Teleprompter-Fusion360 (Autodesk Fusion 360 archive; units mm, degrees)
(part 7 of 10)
sketch "Skizze89" plane through (0, 0, 0) normal (0, 0, -1) x axis (1, 0, 0)
  line L1 (137.0031, -323.7) -> (137.0031, -279.3404)
  line L2 (154.0031, -323.7) -> (137.0031, -323.7)
  line L3 (154.0031, -311.7) -> (154.0031, -323.7)
  line L4 (171.0031, -311.7) -> (154.0031, -311.7)
  line L5 (171.0031, -323.7) -> (171.0031, -311.7)
  line L6 (188.0031, -323.7) -> (171.0031, -323.7)
  line L7 (188.0031, -311.7) -> (188.0031, -323.7)
  line L8 (205.0031, -311.7) -> (188.0031, -311.7)
  line L9 (205.0031, -323.7) -> (205.0031, -311.7)
  line L10 (222.0031, -323.7) -> (205.0031, -323.7)
  line L11 (222.0031, -279.3404) -> (222.0031, -323.7)
  line L12 (374.0031, -255.3404) -> (246.0031, -255.3404)
  line L13 (374.0031, -240.1877) -> (374.0031, -255.3404)
  line L14 (366.2457, -240.1877) -> (374.0031, -240.1877)
  line L15 (362.0031, -220.3404) -> (362.0031, -235.9451)
  line L16 (361.0031, -220.3404) -> (362.0031, -220.3404)
  line L17 (358.0031, -167.3404) -> (358.0031, -217.3404)
  line L18
  line L19 (362.0031, -134.383) -> (362.0031, -164.3404)
  line L20 (374.0031, -130.1404) -> (366.2457, -130.1404)
  line L21 (374.0031, -95.9404) -> (374.0031, -130.1404)
  line L22 (366.2457, -95.9404) -> (374.0031, -95.9404)
  line L23 (362.0031, -65.983) -> (362.0031, -91.6977)
  line L24 (374.0031, -61.7404) -> (366.2457, -61.7404)
  line L25 (374.0031, -27.5404) -> (374.0031, -61.7404)
  line L26 (366.2457, -27.5404) -> (374.0031, -27.5404)
  line L27 (362.0031, 2.417) -> (362.0031, -23.2977)
  line L28 (374.0031, 6.6596) -> (366.2457, 6.6596)
  line L29 (-2.9969, 18.6596) -> (362.0031, 18.6596)
  line L30 (-7.2396, 6.6596) -> (-14.9969, 6.6596)
  line L31 (-2.9969, -23.2977) -> (-2.9969, 2.417)
  line L32 (-14.9969, -27.5404) -> (-7.2396, -27.5404)
  line L33 (-14.9969, -61.7404) -> (-14.9969, -27.5404)
  line L34 (-7.2396, -61.7404) -> (-14.9969, -61.7404)
  line L35 (-2.9969, -91.6977) -> (-2.9969, -65.983)
  line L36 (-14.9969, -95.9404) -> (-7.2396, -95.9404)
  line L37 (-14.9969, -130.1404) -> (-14.9969, -95.9404)
  line L38 (-7.2396, -130.1404) -> (-14.9969, -130.1404)
  line L39 (-2.9969, -164.3404) -> (-2.9969, -134.383)
  line L40 (-2.9968, -164.3404) -> (-2.9969, -164.3404)
  line L41 (0.0031, -217.3404) -> (0.0031, -167.3404)
  line L42 (-2.9969, -220.3404) -> (-2.9968, -220.3404)
  line L43 (-2.9969, -235.9451) -> (-2.9969, -220.3404)
  line L44 (-14.9969, -240.1877) -> (-7.2396, -240.1877)
  line L45 (-14.9969, -255.3404) -> (-14.9969, -240.1877)
  line L46 (113.0031, -255.3404) -> (-14.9969, -255.3404)
  line L47 (300.0031, -190.3404) -> (300.0031, -174.3404)
  line L48 (203.5031, -202.3404) -> (288.0031, -202.3404)
  line L49 (191.5031, -174.3404) -> (191.5031, -190.3404)
  line L50 (288.0031, -162.3404) -> (203.5031, -162.3404)
  line L51 (191.5031, -31.3404) -> (191.5031, -114.3404)
  line L52 (312.0031, -19.3404) -> (203.5031, -19.3404)
  line L53 (324.0031, -114.3404) -> (324.0031, -31.3404)
  line L54 (203.5031, -126.3404) -> (312.0031, -126.3404)
  line L55 (71.0031, -202.3404) -> (155.5031, -202.3404)
  line L56 (59.0031, -174.3404) -> (59.0031, -190.3404)
  line L57 (155.5031, -162.3404) -> (71.0031, -162.3404)
  line L58 (167.5031, -190.3404) -> (167.5031, -174.3404)
  line L59 (47.0031, -126.3404) -> (155.5031, -126.3404)
  line L60 (35.0031, -31.3404) -> (35.0031, -114.3404)
  line L61 (155.5031, -19.3404) -> (47.0031, -19.3404)
  line L62 (167.5031, -114.3404) -> (167.5031, -31.3404)
  line L63 (222.0031, -311.7) -> (137.0031, -311.7)
  line L64 (154.0031, -323.7) -> (137.0031, -311.7)
  line L65 (137.0031, -323.7) -> (154.0031, -311.7)
  line L66 (188.0031, -323.7) -> (171.0031, -311.7)
  line L67 (171.0031, -323.7) -> (188.0031, -311.7)
  line L68 (222.0031, -323.7) -> (205.0031, -311.7)
  line L69 (205.0031, -323.7) -> (222.0031, -311.7)
  circle C1 centre (-8.9969, -246.1877) radius 1.5
  circle C2 centre (368.0031, -246.1877) radius 1.5
  arc A1 centre (246.0031, -279.3404) radius 24 clockwise from (222.0031, -279.3404) to (246.0031, -255.3404)
  arc A2 centre (364.1244, -238.0664) radius 3 clockwise from (366.2457, -240.1877) to (362.0031, -235.9451)
  arc A3 centre (361.0031, -217.3404) radius 3 clockwise from (361.0031, -220.3404) to (358.0031, -217.3404)
  arc A4 centre (361.0031, -167.3404) radius 3 clockwise from (358.0031, -167.3404) to (361.0031, -164.3404)
  arc A5 centre (364.1244, -132.2617) radius 3 clockwise from (362.0031, -134.383) to (366.2457, -130.1404)
  arc A6 centre (364.1244, -93.8191) radius 3 clockwise from (366.2457, -95.9404) to (362.0031, -91.6977)
  arc A7 centre (364.1244, -63.8617) radius 3 clockwise from (362.0031, -65.983) to (366.2457, -61.7404)
  arc A8 centre (364.1244, -25.4191) radius 3 clockwise from (366.2457, -27.5404) to (362.0031, -23.2977)
  arc A9 centre (364.1244, 4.5383) radius 3 clockwise from (362.0031, 2.417) to (366.2457, 6.6596)
  arc A10 centre (362.0031, 6.6596) radius 12 clockwise from (362.0031, 18.6596) to (374.0031, 6.6596)
  arc A11 centre (-2.9969, 6.6596) radius 12 clockwise from (-14.9969, 6.6596) to (-2.9969, 18.6596)
  arc A12 centre (-5.1183, 4.5383) radius 3 clockwise from (-7.2396, 6.6596) to (-2.9969, 2.417)
  arc A13 centre (-5.1183, -25.4191) radius 3 clockwise from (-2.9969, -23.2977) to (-7.2396, -27.5404)
  arc A14 centre (-5.1183, -63.8617) radius 3 clockwise from (-7.2396, -61.7404) to (-2.9969, -65.983)
  arc A15 centre (-5.1183, -93.8191) radius 3 clockwise from (-2.9969, -91.6977) to (-7.2396, -95.9404)
  arc A16 centre (-5.1183, -132.2617) radius 3 clockwise from (-7.2396, -130.1404) to (-2.9969, -134.383)
  arc A17 centre (-2.9969, -167.3404) radius 3 clockwise from (-2.9968, -164.3404) to (0.0031, -167.3404)
  arc A18 centre (-2.9969, -217.3404) radius 3 clockwise from (0.0031, -217.3404) to (-2.9968, -220.3404)
  arc A19 centre (-5.1183, -238.0664) radius 3 clockwise from (-2.9969, -235.9451) to (-7.2396, -240.1877)
  arc A20 centre (113.0031, -279.3404) radius 24 clockwise from (113.0031, -255.3404) to (137.0031, -279.3404)
  circle C3 centre (-8.9969, -44.6404) radius 1.5
  circle C4 centre (368.0031, -44.6404) radius 1.5
  arc A21 centre (288.0031, -190.3404) radius 12 clockwise from (300.0031, -190.3404) to (288.0031, -202.3404)
  arc A22 centre (203.5031, -190.3404) radius 12 clockwise from (203.5031, -202.3404) to (191.5031, -190.3404)
  arc A23 centre (203.5031, -174.3404) radius 12 clockwise from (191.5031, -174.3404) to (203.5031, -162.3404)
  arc A24 centre (288.0031, -174.3404) radius 12 clockwise from (288.0031, -162.3404) to (300.0031, -174.3404)
  arc A25 centre (203.5031, -31.3404) radius 12 clockwise from (191.5031, -31.3404) to (203.5031, -19.3404)
  arc A26 centre (312.0031, -31.3404) radius 12 clockwise from (312.0031, -19.3404) to (324.0031, -31.3404)
  arc A27 centre (312.0031, -114.3404) radius 12 clockwise from (324.0031, -114.3404) to (312.0031, -126.3404)
  arc A28 centre (203.5031, -114.3404) radius 12 clockwise from (203.5031, -126.3404) to (191.5031, -114.3404)
  arc A29 centre (71.0031, -190.3404) radius 12 clockwise from (71.0031, -202.3404) to (59.0031, -190.3404)
  arc A30 centre (71.0031, -174.3404) radius 12 clockwise from (59.0031, -174.3404) to (71.0031, -162.3404)
  arc A31 centre (155.5031, -174.3404) radius 12 clockwise from (155.5031, -162.3404) to (167.5031, -174.3404)
  arc A32 centre (155.5031, -190.3404) radius 12 clockwise from (167.5031, -190.3404) to (155.5031, -202.3404)
  arc A33 centre (47.0031, -114.3404) radius 12 clockwise from (47.0031, -126.3404) to (35.0031, -114.3404)
  arc A34 centre (47.0031, -31.3404) radius 12 clockwise from (35.0031, -31.3404) to (47.0031, -19.3404)
  arc A35 centre (155.5031, -31.3404) radius 12 clockwise from (155.5031, -19.3404) to (167.5031, -31.3404)
  arc A36 centre (155.5031, -114.3404) radius 12 clockwise from (167.5031, -114.3404) to (155.5031, -126.3404)
  circle C5 centre (368.0031, -113.0404) radius 1.5
  circle C6 centre (-8.9969, -113.0404) radius 1.5
  circle C7 centre (145.5031, -317.7) radius 1.5
  circle C8 centre (179.5031, -317.7) radius 1.5
  circle C9 centre (213.5031, -317.7) radius 1.5
  point P142 (222.0031, -311.7)
  point P143 (137.0031, -311.7)
  point P6 (154.0031, -323.7)
  point P144 (154.0031, -323.7)
  point P7 (154.0031, -311.7)
  point P145 (154.0031, -311.7)
  point P5 (137.0031, -323.7)
  point P146 (137.0031, -323.7)
  point P8 (171.0031, -311.7)
  point P147 (171.0031, -311.7)
  point P10 (188.0031, -323.7)
  point P148 (188.0031, -323.7)
  point P11 (188.0031, -311.7)
  point P149 (188.0031, -311.7)
  point P9 (171.0031, -323.7)
  point P150 (171.0031, -323.7)
  point P12 (205.0031, -311.7)
  point P151 (205.0031, -311.7)
  point P14 (222.0031, -323.7)
  point P152 (222.0031, -323.7)
  point P13 (205.0031, -323.7)
  point P153 (205.0031, -323.7)
  point P154 (145.5031, -317.7)
  point P155 (179.5031, -317.7)
  point P156 (213.5031, -317.7)
  coincident L11 P142
  perpendicular L11 L63
  coincident L1 P143
  coincident P6 P144
  coincident P7 P145
  coincident P5 P146
  coincident P8 P147
  coincident P10 P148
  coincident P11 P149
  coincident P9 P150
  coincident P12 P151
  coincident P14 P152
  coincident P13 P153
  parallel L67 L69
  midpoint L64 P154
  midpoint L67 P155
  midpoint L68 P156
  dimension "d503" diameter C7 = 3
  dimension "d504" diameter C8 = 3
  dimension "d505" diameter C9 = 3
extrude "Extrusion90" cut sketch "Skizze89" profile of C7 C8 C9 against normal blind 25
chamfer "Fase6" distance 3
offset_faces "Flächen versetzen3" distance -2
sketch "Skizze90" plane through (374.0031, 0, 0) normal (1, 0, 0) x axis (0, 1, 0)
  line L1 (220.3404, 0) -> (220.3404, 14.2357)
  line L2 (240.1877, 0) -> (220.3404, 0)
  line L3 (240.1877, 7.7574) -> (240.1877, 0)
  line L4 (255.3404, 12) -> (244.4304, 12)
  line L5 (255.3404, 24) -> (255.3404, 12)
  line L6 (136.7133, 249.9055) -> (240.4466, 41.3358)
  line L7 (123.6681, 256.7925) -> (126.9563, 256.521)
  line L8
  line L9 (-14.6596, 267) -> (-0.4576, 267)
  line L10 (-18.6596, 251.0692) -> (-18.6596, 263)
  line L11 (66.5768, 160.8622) -> (-15.1449, 242.5839)
  line L12 (70.0916, 39) -> (70.0916, 152.3769)
  line L13 (5.3404, 27) -> (58.0916, 27)
  line L14 (-6.6596, 0) -> (-6.6596, 15)
  line L15 (27.5404, 0) -> (-6.6596, 0)
  line L16 (27.5404, 7.7574) -> (27.5404, 0)
  line L17 (57.4977, 12) -> (31.783, 12)
  line L18 (61.7404, 0) -> (61.7404, 7.7574)
  line L19 (95.9404, 0) -> (61.7404, 0)
  line L20 (95.9404, 7.7574) -> (95.9404, 0)
  line L21 (125.8977, 12) -> (100.183, 12)
  line L22 (130.1404, 0) -> (130.1404, 7.7574)
  line L23 (164.3404, 0) -> (130.1404, 0)
  line L24 (164.3404, 14.2357) -> (164.3404, 0)
  line L25 (214.6835, 18) -> (169.9972, 18)
  line L26 (137.2147, 129.8223) -> (176.4327, 90.6042)
  line L27 (133.7, 177.9426) -> (133.7, 138.3075)
  line L28 (195.6625, 104.4333) -> (156.4445, 183.2864)
  line L29 (97.7, 198.3075) -> (97.7, 235.8456)
  line L30 (36.2984, 230.7386) -> (77.2147, 189.8223)
  line L31 (86.6874, 247.805) -> (45.7711, 251.1832)
  line L32 (113.9426, 213.455) -> (117.4574, 213.455)
  line L33 (109.7, 240.7124) -> (109.7, 217.6976)
  line L34 (117.4574, 244.955) -> (113.9426, 244.955)
  line L35 (121.7, 217.6976) -> (121.7, 240.7124)
  line L36 (121.7, 154.6976) -> (121.7, 177.7124)
  line L37 (113.9426, 150.455) -> (117.4574, 150.455)
  line L38 (109.7, 177.7124) -> (109.7, 154.6976)
  line L39 (117.4574, 181.955) -> (113.9426, 181.955)
  line L40 (167.9537, 59.4853) -> (114.5768, 112.8622)
  line L41 (106.0916, 39) -> (159.4684, 39)
  line L42 (94.0916, 104.3769) -> (94.0916, 51)
  line L43 (-0.4576, 267) -> (-14.6596, 267)
  line L44 (-14.6596, 267) -> (-0.4576, 267)
  line L45 (-18.6596, 263.0692) -> (-15.8312, 265.8976)
  line L46 (237.3593, 7.0503) -> (-18.6596, 263.0692)
  line L47 (240.1877, 9.8787) -> (237.3593, 7.0503)
  line L48 (-15.8312, 265.8976) -> (240.1877, 9.8787)
  line L49 (64.4555, 158.7408) -> (-17.2662, 240.4626)
  line L50 (67.0916, 39) -> (67.0916, 152.3769)
  line L51 (5.3404, 30) -> (58.0916, 30)
  line L52 (-9.6596, -3) -> (-9.6596, 15)
  line L53 (30.5404, -3) -> (-9.6596, -3)
  line L54 (30.5404, 7.7574) -> (30.5404, -3)
  line L55 (57.4977, 9) -> (31.783, 9)
  line L56 (58.7404, -3) -> (58.7404, 7.7574)
  line L57 (98.9404, -3) -> (58.7404, -3)
  line L58 (98.9404, 7.7574) -> (98.9404, -3)
  line L59 (125.8977, 9) -> (100.183, 9)
  line L60 (127.1404, -3) -> (127.1404, 7.7574)
  line L61 (167.3404, -3) -> (127.1404, -3)
  line L62 (167.3404, 14.2357) -> (167.3404, -3)
  line L63 (214.6835, 15) -> (169.9972, 15)
  line L64 (217.3404, -3) -> (217.3404, 14.2357)
  line L65 (243.1877, -3) -> (217.3404, -3)
  line L66 (243.1877, 7.7574) -> (243.1877, -3)
  line L67 (258.3404, 9) -> (244.4304, 9)
  line L68 (258.3404, 24) -> (258.3404, 9)
  line L69 (139.3994, 251.2415) -> (243.1328, 42.6718)
  line L70 (124.0313, 259.7727) -> (127.2031, 259.5108)
  line L71 (0.7767, 269.9491) -> (121.8305, 259.9544)
  line L72 (-14.6596, 270) -> (-0.4576, 270)
  line L73 (-21.6596, 251.0692) -> (-21.6596, 263)
  line L74 (-3.2487, 250.3282) -> (-15.1903, 238.3866)
  line L75 (2.931, 240.508) -> (-13.069, 240.508)
  line L76 (-3.2487, 250.3282) -> (-3.2487, 270)
  arc A1 centre (214.6835, 10) radius 8 clockwise from (214.6835, 18) to (218.9345, 16.7771)
  arc A2 centre (217.3404, 14.2357) radius 3 clockwise from (218.9345, 16.7771) to (220.3404, 14.2357)
  arc A3 centre (242.3091, 9.8787) radius 3 clockwise from (240.1877, 7.7574) to (244.4304, 12)
  arc A4 centre (243.3404, 24) radius 12 clockwise from (247.2657, 35.3398) to (255.3404, 24)
  arc A5 centre (251.1911, 46.6796) radius 12 clockwise from (247.2657, 35.3398) to (240.4466, 41.3358)
  arc A6 centre (125.9689, 244.5617) radius 12 clockwise from (126.9563, 256.521) to (136.7133, 249.9055)
  arc A7 centre (121.7, 244.955) radius 12 clockwise from (121.7, 256.955) to (123.6681, 256.7925)
  arc A8 centre (-0.4576, 255) radius 12 clockwise from (-0.4576, 267) to (0.5298, 266.9593)
  arc A9 centre (-14.6596, 263) radius 4 clockwise from (-18.6596, 263) to (-14.6596, 267)
  arc A10 centre (-6.6596, 251.0692) radius 12 clockwise from (-15.1449, 242.5839) to (-18.6596, 251.0692)
  arc A11 centre (58.0916, 152.3769) radius 12 clockwise from (66.5768, 160.8622) to (70.0916, 152.3769)
  arc A12 centre (58.0916, 39) radius 12 clockwise from (70.0916, 39) to (58.0916, 27)
  arc A13 centre (5.3404, 15) radius 12 clockwise from (-6.6596, 15) to (5.3404, 27)
  arc A14 centre (29.6617, 9.8787) radius 3 clockwise from (27.5404, 7.7574) to (31.783, 12)
  arc A15 centre (59.6191, 9.8787) radius 3 clockwise from (57.4977, 12) to (61.7404, 7.7574)
  arc A16 centre (98.0617, 9.8787) radius 3 clockwise from (95.9404, 7.7574) to (100.183, 12)
  arc A17 centre (128.0191, 9.8787) radius 3 clockwise from (125.8977, 12) to (130.1404, 7.7574)
  arc A18 centre (167.3404, 14.2357) radius 3 clockwise from (164.3404, 14.2357) to (165.7463, 16.7771)
  arc A19 centre (169.9972, 10) radius 8 clockwise from (165.7463, 16.7771) to (169.9972, 18)
  circle C1 centre (140.2404, 6) radius 1.5
  circle C2 centre (115.7, 197.705) radius 1.5
  arc A20 centre (184.918, 99.0895) radius 12 clockwise from (195.6625, 104.4333) to (176.4327, 90.6042)
  arc A21 centre (145.7, 138.3075) radius 12 clockwise from (137.2147, 129.8223) to (133.7, 138.3075)
  arc A22 centre (145.7, 177.9426) radius 12 clockwise from (133.7, 177.9426) to (156.4445, 183.2864)
  arc A23 centre (85.7, 235.8456) radius 12 clockwise from (86.6874, 247.805) to (97.7, 235.8456)
  arc A24 centre (85.7, 198.3075) radius 12 clockwise from (97.7, 198.3075) to (77.2147, 189.8223)
  arc A25 centre (44.7837, 239.2239) radius 12 clockwise from (36.2984, 230.7386) to (45.7711, 251.1832)
  arc A26 centre (111.8213, 215.5763) radius 3 clockwise from (113.9426, 213.455) to (109.7, 217.6976)
  arc A27 centre (111.8213, 242.8337) radius 3 clockwise from (109.7, 240.7124) to (113.9426, 244.955)
  arc A28 centre (119.5787, 242.8337) radius 3 clockwise from (117.4574, 244.955) to (121.7, 240.7124)
  arc A29 centre (119.5787, 215.5763) radius 3 clockwise from (121.7, 217.6976) to (117.4574, 213.455)
  arc A30 centre (119.5787, 152.5763) radius 3 clockwise from (121.7, 154.6976) to (117.4574, 150.455)
  arc A31 centre (111.8213, 152.5763) radius 3 clockwise from (113.9426, 150.455) to (109.7, 154.6976)
  arc A32 centre (111.8213, 179.8337) radius 3 clockwise from (109.7, 177.7124) to (113.9426, 181.955)
  arc A33 centre (119.5787, 179.8337) radius 3 clockwise from (117.4574, 181.955) to (121.7, 177.7124)
  arc A34 centre (159.4684, 51) radius 12 clockwise from (167.9537, 59.4853) to (159.4684, 39)
  arc A35 centre (106.0916, 51) radius 12 clockwise from (106.0916, 39) to (94.0916, 51)
  arc A36 centre (106.0916, 104.3769) radius 12 clockwise from (94.0916, 104.3769) to (114.5768, 112.8622)
  circle C3 centre (230.2641, 6) radius 1.5
  circle C4 centre (10.4404, 6) radius 1.5
  circle C5 centre (78.8404, 6) radius 1.5
  arc A37 centre (-6.6596, 251.0692) radius 15 clockwise from (-17.2662, 240.4626) to (-21.6596, 251.0692)
  arc A38 centre (58.0916, 152.3769) radius 9 clockwise from (64.4555, 158.7408) to (67.0916, 152.3769)
  arc A39 centre (58.0916, 39) radius 9 clockwise from (67.0916, 39) to (58.0916, 30)
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  point P196 (-3.2487, 270)
  point P197 (-13.069, 240.508)
  point P200 (-15.1903, 238.3866)
  coincident L72 P196
  perpendicular L72 L76
  horizontal L75
  coincident L11 P197
  coincident L49 P200
  coincident P197 L74
  dimension "d510" = 3
  dimension "d511" angle L74 L75 = 45
extrude "Extrusion91" new body sketch "Skizze90" against normal blind 12 bodies "3DP-Glas-Abdeckung Right"
sketch "Skizze91" plane through (374.0031, 0, 0) normal (1, 0, 0) x axis (0, 1, 0)
  line L1 (-21.6596, 251.0692) -> (-21.6596, 263)
  line L2 (-15.1903, 238.3866) -> (-17.2662, 240.4626)
  line L3 (-13.069, 240.508) -> (-15.1903, 238.3866)
  line L4 (-15.1449, 242.5839) -> (-13.069, 240.508)
  line L5 (-18.6596, 263) -> (-18.6596, 251.0692)
  line L6 (-18.6596, 263.0692) -> (-18.659, 263.0686)
  line L7 (-18.659, 263.0698) -> (-18.6596, 263.0692)
  line L8 (-3.2487, 267) -> (-14.6596, 267)
  line L9 (-3.2487, 270) -> (-3.2487, 267)
  line L10 (-14.6596, 270) -> (-3.2487, 270)
  line L11 (-10.2782, 243.2988) -> (-15.1903, 238.3866)
  line L12 (-3.2487, 260.2693) -> (-3.2487, 270)
  arc A1 centre (-14.6596, 263) radius 7 clockwise from (-21.6596, 263) to (-14.6596, 270)
  arc A2 centre (-6.6596, 251.0692) radius 15 clockwise from (-17.2662, 240.4626) to (-21.6596, 251.0692)
  arc A3 centre (-6.6596, 251.0692) radius 12 clockwise from (-15.1449, 242.5839) to (-18.6596, 251.0692)
  arc A4 centre (-14.6596, 263) radius 4 clockwise from (-18.6596, 263) to (-18.659, 263.0686)
  arc A5 centre (-14.6596, 263) radius 4 clockwise from (-18.659, 263.0698) to (-14.6596, 267)
  arc A6 centre (-27.2487, 260.2693) radius 24 clockwise from (-3.2487, 260.2693) to (-10.2782, 243.2988)
  point P8 (-15.1903, 238.3866)
  point P19 (-15.1903, 238.3866)
  point P18 (-3.2487, 270)
  point P20 (-3.2487, 270)
  coincident P8 P19
  perpendicular L4 L11
  coincident P18 P20
  perpendicular L10 L12
  tangent L12 A6
  tangent L11 A6
  dimension "d515" radius A6 = 24
extrude "Extrusion92" add sketch "Skizze91" along normal blind 4
sketch "Skizze92" plane through (378.0031, 0, 0) normal (1, 0, 0) x axis (0, 1, 0)
  line L1 (-14.6596, 270) -> (-3.2487, 270)
  line L2 (-21.6596, 251.0692) -> (-21.6596, 263)
  line L3 (-15.1903, 238.3866) -> (-17.2662, 240.4626)
  line L4 (-10.2782, 243.2988) -> (-15.1903, 238.3866)
  line L5 (-3.2487, 270) -> (-3.2487, 260.2693)
  line L6 (-18.6596, 263.0692) -> (-15.8312, 265.8976)
  line L7 (237.3593, 7.0503) -> (-18.6596, 263.0692)
  line L8 (240.1877, 9.8787) -> (237.3593, 7.0503)
  line L9 (-15.8312, 265.8976) -> (240.1877, 9.8787)
  line L10 (106.0916, 39) -> (159.4684, 39)
  line L11 (94.0916, 104.3769) -> (94.0916, 51)
  line L12 (167.9537, 59.4853) -> (114.5768, 112.8622)
  line L13 (130.1404, 0) -> (130.1404, 7.7574)
  line L14 (164.3404, 0) -> (130.1404, 0)
  line L15 (164.3404, 11.3932) -> (164.3404, 0)
  line L16 (214.6835, 16) -> (169.9972, 16)
  line L17 (220.3404, 0) -> (220.3404, 11.3932)
  line L18 (240.1877, 0) -> (220.3404, 0)
  line L19 (240.1877, 3.939) -> (240.1877, 0)
  line L20 (-18.6596, 262.7863) -> (240.1877, 3.939)
  line L21 (-18.6596, 251.0692) -> (-18.6596, 262.7863)
  line L22 (66.5768, 160.8622) -> (-15.1449, 242.5839)
  line L23 (70.0916, 39) -> (70.0916, 152.3769)
  line L24 (5.3404, 27) -> (58.0916, 27)
  line L25 (-6.6596, 0) -> (-6.6596, 15)
  line L26 (27.5404, 0) -> (-6.6596, 0)
  line L27 (27.5404, 7.7574) -> (27.5404, 0)
  line L28 (57.4977, 12) -> (31.783, 12)
  line L29 (61.7404, 0) -> (61.7404, 7.7574)
  line L30 (95.9404, 0) -> (61.7404, 0)
  line L31 (95.9404, 7.7574) -> (95.9404, 0)
  line L32 (125.8977, 12) -> (100.183, 12)
  arc A1 centre (-14.6596, 263) radius 7 clockwise from (-21.6596, 263) to (-14.6596, 270)
  arc A2 centre (-6.6596, 251.0692) radius 15 clockwise from (-17.2662, 240.4626) to (-21.6596, 251.0692)
  arc A3 centre (-27.2487, 260.2693) radius 24 clockwise from (-3.2487, 260.2693) to (-10.2782, 243.2988)
  circle C1 centre (140.2404, 6) radius 1.5
  arc A4 centre (106.0916, 51) radius 12 clockwise from (106.0916, 39) to (94.0916, 51)
  arc A5 centre (106.0916, 104.3769) radius 12 clockwise from (94.0916, 104.3769) to (114.5768, 112.8622)
  arc A6 centre (159.4684, 51) radius 12 clockwise from (167.9537, 59.4853) to (159.4684, 39)
  circle C2 centre (230.2641, 6) radius 1.5
  circle C3 centre (10.4404, 6) radius 1.5
  circle C4 centre (78.8404, 6) radius 1.5
  arc A7 centre (128.0191, 9.8787) radius 3 clockwise from (125.8977, 12) to (130.1404, 7.7574)
  arc A8 centre (167.3404, 11.3932) radius 3 clockwise from (164.3404, 11.3932) to (164.6835, 12.7865)
  arc A9 centre (169.9972, 10) radius 6 clockwise from (164.6835, 12.7865) to (169.9972, 16)
  arc A10 centre (214.6835, 10) radius 6 clockwise from (214.6835, 16) to (219.9972, 12.7865)
  arc A11 centre (217.3404, 11.3932) radius 3 clockwise from (219.9972, 12.7865) to (220.3404, 11.3932)
  arc A12 centre (-6.6596, 251.0692) radius 12 clockwise from (-15.1449, 242.5839) to (-18.6596, 251.0692)
  arc A13 centre (58.0916, 152.3769) radius 12 clockwise from (66.5768, 160.8622) to (70.0916, 152.3769)
  arc A14 centre (58.0916, 39) radius 12 clockwise from (70.0916, 39) to (58.0916, 27)
  arc A15 centre (5.3404, 15) radius 12 clockwise from (-6.6596, 15) to (5.3404, 27)
  arc A16 centre (29.6617, 9.8787) radius 3 clockwise from (27.5404, 7.7574) to (31.783, 12)
  arc A17 centre (59.6191, 9.8787) radius 3 clockwise from (57.4977, 12) to (61.7404, 7.7574)
  arc A18 centre (98.0617, 9.8787) radius 3 clockwise from (95.9404, 7.7574) to (100.183, 12)
  circle C5 centre (-12.9869, 249.5514) radius 2
  dimension "d518" diameter C5 = 4
extrude "Extrusion93" cut sketch "Skizze92" profile of C5 against normal blind 10
work_plane "Arbeitsebene4"
sketch "Skizze93" plane through (374.0031, 0, 0) normal (1, 0, 0) x axis (0, 1, 0)
  line L1 (220.3404, 0) -> (220.3404, 14.2357)
  line L2 (240.1877, 0) -> (220.3404, 0)
  line L3 (240.1877, 7.7574) -> (240.1877, 0)
  line L4 (255.3404, 12) -> (244.4304, 12)
  line L5 (255.3404, 24) -> (255.3404, 12)
  line L6 (136.7133, 249.9055) -> (240.4466, 41.3358)
  line L7 (123.6681, 256.7925) -> (126.9563, 256.521)
  line L8
  line L9 (-14.6596, 267) -> (-0.4576, 267)
  line L10 (-18.6596, 251.0692) -> (-18.6596, 263)
  line L11 (66.5768, 160.8622) -> (-15.1449, 242.5839)
  line L12 (70.0916, 39) -> (70.0916, 152.3769)
  line L13 (5.3404, 27) -> (58.0916, 27)
  line L14 (-6.6596, 0) -> (-6.6596, 15)
  line L15 (27.5404, 0) -> (-6.6596, 0)
  line L16 (27.5404, 7.7574) -> (27.5404, 0)
  line L17 (57.4977, 12) -> (31.783, 12)
  line L18 (61.7404, 0) -> (61.7404, 7.7574)
  line L19 (95.9404, 0) -> (61.7404, 0)
  line L20 (95.9404, 7.7574) -> (95.9404, 0)
  line L21 (125.8977, 12) -> (100.183, 12)
  line L22 (130.1404, 0) -> (130.1404, 7.7574)
  line L23 (164.3404, 0) -> (130.1404, 0)
  line L24 (164.3404, 14.2357) -> (164.3404, 0)
  line L25 (214.6835, 18) -> (169.9972, 18)
  line L26 (137.2147, 129.8223) -> (176.4327, 90.6042)
  line L27 (133.7, 177.9426) -> (133.7, 138.3075)
  line L28 (195.6625, 104.4333) -> (156.4445, 183.2864)
  line L29 (97.7, 198.3075) -> (97.7, 235.8456)
  line L30 (36.2984, 230.7386) -> (77.2147, 189.8223)
  line L31 (86.6874, 247.805) -> (45.7711, 251.1832)
  line L32 (113.9426, 213.455) -> (117.4574, 213.455)
  line L33 (109.7, 240.7124) -> (109.7, 217.6976)
  line L34 (117.4574, 244.955) -> (113.9426, 244.955)
  line L35 (121.7, 217.6976) -> (121.7, 240.7124)
  line L36 (121.7, 154.6976) -> (121.7, 177.7124)
  line L37 (113.9426, 150.455) -> (117.4574, 150.455)
  line L38 (109.7, 177.7124) -> (109.7, 154.6976)
  line L39 (117.4574, 181.955) -> (113.9426, 181.955)
  line L40 (167.9537, 59.4853) -> (114.5768, 112.8622)
  line L41 (106.0916, 39) -> (159.4684, 39)
  line L42 (94.0916, 104.3769) -> (94.0916, 51)
  line L43 (253.9338, 29.6373) -> (136.5623, 250.199)
  arc A1 centre (214.6835, 10) radius 8 clockwise from (214.6835, 18) to (218.9345, 16.7771)
  arc A2 centre (217.3404, 14.2357) radius 3 clockwise from (218.9345, 16.7771) to (220.3404, 14.2357)
  arc A3 centre (242.3091, 9.8787) radius 3 clockwise from (240.1877, 7.7574) to (244.4304, 12)
  arc A4 centre (243.3404, 24) radius 12 clockwise from (247.2657, 35.3398) to (255.3404, 24)
  arc A5 centre (251.1911, 46.6796) radius 12 clockwise from (247.2657, 35.3398) to (240.4466, 41.3358)
  arc A6 centre (125.9689, 244.5617) radius 12 clockwise from (126.9563, 256.521) to (136.7133, 249.9055)
  arc A7 centre (121.7, 244.955) radius 12 clockwise from (121.7, 256.955) to (123.6681, 256.7925)
  arc A8 centre (-0.4576, 255) radius 12 clockwise from (-0.4576, 267) to (0.5298, 266.9593)
  arc A9 centre (-14.6596, 263) radius 4 clockwise from (-18.6596, 263) to (-14.6596, 267)
  arc A10 centre (-6.6596, 251.0692) radius 12 clockwise from (-15.1449, 242.5839) to (-18.6596, 251.0692)
  arc A11 centre (58.0916, 152.3769) radius 12 clockwise from (66.5768, 160.8622) to (70.0916, 152.3769)
  arc A12 centre (58.0916, 39) radius 12 clockwise from (70.0916, 39) to (58.0916, 27)
  arc A13 centre (5.3404, 15) radius 12 clockwise from (-6.6596, 15) to (5.3404, 27)
  arc A14 centre (29.6617, 9.8787) radius 3 clockwise from (27.5404, 7.7574) to (31.783, 12)
  arc A15 centre (59.6191, 9.8787) radius 3 clockwise from (57.4977, 12) to (61.7404, 7.7574)
  arc A16 centre (98.0617, 9.8787) radius 3 clockwise from (95.9404, 7.7574) to (100.183, 12)
  arc A17 centre (128.0191, 9.8787) radius 3 clockwise from (125.8977, 12) to (130.1404, 7.7574)
  arc A18 centre (167.3404, 14.2357) radius 3 clockwise from (164.3404, 14.2357) to (165.7463, 16.7771)
  arc A19 centre (169.9972, 10) radius 8 clockwise from (165.7463, 16.7771) to (169.9972, 18)
  circle C1 centre (140.2404, 6) radius 1.5
  circle C2 centre (115.7, 197.705) radius 1.5
  arc A20 centre (184.918, 99.0895) radius 12 clockwise from (195.6625, 104.4333) to (176.4327, 90.6042)
  arc A21 centre (145.7, 138.3075) radius 12 clockwise from (137.2147, 129.8223) to (133.7, 138.3075)
  arc A22 centre (145.7, 177.9426) radius 12 clockwise from (133.7, 177.9426) to (156.4445, 183.2864)
  arc A23 centre (85.7, 235.8456) radius 12 clockwise from (86.6874, 247.805) to (97.7, 235.8456)
  arc A24 centre (85.7, 198.3075) radius 12 clockwise from (97.7, 198.3075) to (77.2147, 189.8223)
  arc A25 centre (44.7837, 239.2239) radius 12 clockwise from (36.2984, 230.7386) to (45.7711, 251.1832)
  arc A26 centre (111.8213, 215.5763) radius 3 clockwise from (113.9426, 213.455) to (109.7, 217.6976)
  arc A27 centre (111.8213, 242.8337) radius 3 clockwise from (109.7, 240.7124) to (113.9426, 244.955)
  arc A28 centre (119.5787, 242.8337) radius 3 clockwise from (117.4574, 244.955) to (121.7, 240.7124)
  arc A29 centre (119.5787, 215.5763) radius 3 clockwise from (121.7, 217.6976) to (117.4574, 213.455)
  arc A30 centre (119.5787, 152.5763) radius 3 clockwise from (121.7, 154.6976) to (117.4574, 150.455)
  arc A31 centre (111.8213, 152.5763) radius 3 clockwise from (113.9426, 150.455) to (109.7, 154.6976)
  arc A32 centre (111.8213, 179.8337) radius 3 clockwise from (109.7, 177.7124) to (113.9426, 181.955)
  arc A33 centre (119.5787, 179.8337) radius 3 clockwise from (117.4574, 181.955) to (121.7, 177.7124)
  arc A34 centre (159.4684, 51) radius 12 clockwise from (167.9537, 59.4853) to (159.4684, 39)
  arc A35 centre (106.0916, 51) radius 12 clockwise from (106.0916, 39) to (94.0916, 51)
  arc A36 centre (106.0916, 104.3769) radius 12 clockwise from (94.0916, 104.3769) to (114.5768, 112.8622)
  circle C3 centre (230.2641, 6) radius 1.5
  circle C4 centre (10.4404, 6) radius 1.5
  circle C5 centre (78.8404, 6) radius 1.5
  point P121 (136.5623, 250.199)
  point P122 (253.9338, 29.6373)
  tangent A6 L43
  tangent A4 L43
  coincident A6 P121
  coincident A4 P122
extrude "Extrusion94" add sketch "Skizze93" profile of A4 A5 L6 A6 L43 against normal blind 12
sketch "Skizze94" plane through (-14.9969, 0, 0) normal (-1, 0, 0) x axis (0, -1, 0)
  line L1 (-156.4445, 183.2864) -> (-195.6625, 104.4333)
  line L2 (-133.7, 138.3075) -> (-133.7, 177.9426)
  line L3 (-176.4327, 90.6042) -> (-137.2147, 129.8223)
  line L4 (-45.7711, 251.1832) -> (-86.6874, 247.805)
  line L5 (-77.2147, 189.8223) -> (-36.2984, 230.7386)
  line L6 (-97.7, 235.8456) -> (-97.7, 198.3075)
  line L7 (-117.4574, 213.455) -> (-113.9426, 213.455)
  line L8 (-121.7, 240.7124) -> (-121.7, 217.6976)
  line L9 (-113.9426, 244.955) -> (-117.4574, 244.955)
  line L10 (-109.7, 217.6976) -> (-109.7, 240.7124)
  line L11 (-121.7, 177.7124) -> (-121.7, 154.6976)
  line L12 (-113.9426, 181.955) -> (-117.4574, 181.955)
  line L13 (-109.7, 154.6976) -> (-109.7, 177.7124)
  line L14 (-117.4574, 150.455) -> (-113.9426, 150.455)
  line L15 (-114.5768, 112.8622) -> (-167.9537, 59.4853)
  line L16 (-94.0916, 51) -> (-94.0916, 104.3769)
  line L17 (-159.4684, 39) -> (-106.0916, 39)
  line L18 (-240.1877, 0) -> (-240.1877, 7.7574)
  line L19 (-220.3404, 0) -> (-240.1877, 0)
  line L20 (-220.3404, 11.3932) -> (-220.3404, 0)
  line L21 (-169.9972, 16) -> (-214.6835, 16)
  line L22 (-164.3404, 0) -> (-164.3404, 11.3932)
  line L23 (-130.1404, 0) -> (-164.3404, 0)
  line L24 (-130.1404, 7.7574) -> (-130.1404, 0)
  line L25 (-100.183, 12) -> (-125.8977, 12)
  line L26 (-95.9404, 0) -> (-95.9404, 7.7574)
  line L27 (-61.7404, 0) -> (-95.9404, 0)
  line L28 (-61.7404, 7.7574) -> (-61.7404, 0)
  line L29 (-31.783, 12) -> (-57.4977, 12)
  line L30 (-27.5404, 0) -> (-27.5404, 7.7574)
  line L31 (6.6596, 0) -> (-27.5404, 0)
  line L32 (6.6596, 15) -> (6.6596, 0)
  line L33 (-58.0916, 27) -> (-5.3404, 27)
  line L34 (-70.0916, 152.3769) -> (-70.0916, 39)
  line L35 (15.1449, 242.5839) -> (-66.5768, 160.8622)
  line L36 (18.6596, 263) -> (18.6596, 251.0692)
  line L37 (0.4576, 267) -> (14.6596, 267)
  line L38 (-121.7, 256.955) -> (-0.5298, 266.9593)
  line L39 (-126.9563, 256.521) -> (-123.6681, 256.7925)
  line L40 (-240.4466, 41.3358) -> (-136.7133, 249.9055)
  line L41 (-255.3404, 12) -> (-255.3404, 24)
  line L42 (-244.4304, 12) -> (-255.3404, 12)
  line L43 (-176.4327, 90.6042) -> (-137.2147, 129.8223)
  line L44 (-156.4445, 183.2864) -> (-195.6625, 104.4333)
  line L45 (-133.7, 138.3075) -> (-133.7, 177.9426)
  line L46 (-97.7, 235.8456) -> (-97.7, 198.3075)
  line L47 (-45.7711, 251.1832) -> (-86.6874, 247.805)
  line L48 (-77.2147, 189.8223) -> (-36.2984, 230.7386)
  line L49 (-117.4574, 213.455) -> (-113.9426, 213.455)
  line L50 (-121.7, 240.7124) -> (-121.7, 217.6976)
  line L51 (-113.9426, 244.955) -> (-117.4574, 244.955)
  line L52 (-109.7, 217.6976) -> (-109.7, 240.7124)
  line L53 (-121.7, 177.7124) -> (-121.7, 154.6976)
  line L54 (-113.9426, 181.955) -> (-117.4574, 181.955)
  line L55 (-109.7, 154.6976) -> (-109.7, 177.7124)
  line L56 (-117.4574, 150.455) -> (-113.9426, 150.455)
  line L57 (16.2993, 266.6485) -> (-239.478, 10.8712)
  line L58 (0.4576, 267) -> (14.6596, 267)
  line L59 (-121.7, 256.955) -> (-0.5298, 266.9593)
  line L60 (-126.9563, 256.521) -> (-123.6681, 256.7925)
  line L61 (-253.9338, 29.6373) -> (-136.5623, 250.199)
  line L62 (-255.3404, 12) -> (-255.3404, 24)
  line L63 (-244.4304, 12) -> (-255.3404, 12)
  circle C1 centre (-140.2404, 6) radius 1.5
  circle C2 centre (-115.7, 197.705) radius 1.5
  arc A1 centre (-184.918, 99.0895) radius 12 clockwise from (-176.4327, 90.6042) to (-195.6625, 104.4333)
  arc A2 centre (-145.7, 177.9426) radius 12 clockwise from (-156.4445, 183.2864) to (-133.7, 177.9426)
  arc A3 centre (-145.7, 138.3075) radius 12 clockwise from (-133.7, 138.3075) to (-137.2147, 129.8223)
  arc A4 centre (-85.7, 235.8456) radius 12 clockwise from (-97.7, 235.8456) to (-86.6874, 247.805)
  arc A5 centre (-44.7837, 239.2239) radius 12 clockwise from (-45.7711, 251.1832) to (-36.2984, 230.7386)
  arc A6 centre (-85.7, 198.3075) radius 12 clockwise from (-77.2147, 189.8223) to (-97.7, 198.3075)
  arc A7 centre (-119.5787, 215.5763) radius 3 clockwise from (-117.4574, 213.455) to (-121.7, 217.6976)
  arc A8 centre (-119.5787, 242.8337) radius 3 clockwise from (-121.7, 240.7124) to (-117.4574, 244.955)
  arc A9 centre (-111.8213, 242.8337) radius 3 clockwise from (-113.9426, 244.955) to (-109.7, 240.7124)
  arc A10 centre (-111.8213, 215.5763) radius 3 clockwise from (-109.7, 217.6976) to (-113.9426, 213.455)
  arc A11 centre (-119.5787, 179.8337) radius 3 clockwise from (-121.7, 177.7124) to (-117.4574, 181.955)
  arc A12 centre (-111.8213, 179.8337) radius 3 clockwise from (-113.9426, 181.955) to (-109.7, 177.7124)
  arc A13 centre (-111.8213, 152.5763) radius 3 clockwise from (-109.7, 154.6976) to (-113.9426, 150.455)
  arc A14 centre (-119.5787, 152.5763) radius 3 clockwise from (-117.4574, 150.455) to (-121.7, 154.6976)
  arc A15 centre (-106.0916, 104.3769) radius 12 clockwise from (-114.5768, 112.8622) to (-94.0916, 104.3769)
  arc A16 centre (-106.0916, 51) radius 12 clockwise from (-94.0916, 51) to (-106.0916, 39)
  arc A17 centre (-159.4684, 51) radius 12 clockwise from (-159.4684, 39) to (-167.9537, 59.4853)
  circle C3 centre (-230.2641, 6) radius 1.5
  circle C4 centre (-10.4404, 6) radius 1.5
  circle C5 centre (-78.8404, 6) radius 1.5
  arc A18 centre (-242.3091, 9.8787) radius 3 clockwise from (-244.4304, 12) to (-240.1877, 7.7574)
  arc A19 centre (-217.3404, 11.3932) radius 3 clockwise from (-220.3404, 11.3932) to (-219.9972, 12.7865)
  arc A20 centre (-214.6835, 10) radius 6 clockwise from (-219.9972, 12.7865) to (-214.6835, 16)
  arc A21 centre (-169.9972, 10) radius 6 clockwise from (-169.9972, 16) to (-164.6835, 12.7865)
  arc A22 centre (-167.3404, 11.3932) radius 3 clockwise from (-164.6835, 12.7865) to (-164.3404, 11.3932)
  arc A23 centre (-128.0191, 9.8787) radius 3 clockwise from (-130.1404, 7.7574) to (-125.8977, 12)
  arc A24 centre (-98.0617, 9.8787) radius 3 clockwise from (-100.183, 12) to (-95.9404, 7.7574)
  arc A25 centre (-59.6191, 9.8787) radius 3 clockwise from (-61.7404, 7.7574) to (-57.4977, 12)
  arc A26 centre (-29.6617, 9.8787) radius 3 clockwise from (-31.783, 12) to (-27.5404, 7.7574)
  arc A27 centre (-5.3404, 15) radius 12 clockwise from (-5.3404, 27) to (6.6596, 15)
  arc A28 centre (-58.0916, 39) radius 12 clockwise from (-58.0916, 27) to (-70.0916, 39)
  arc A29 centre (-58.0916, 152.3769) radius 12 clockwise from (-70.0916, 152.3769) to (-66.5768, 160.8622)
  arc A30 centre (6.6596, 251.0692) radius 12 clockwise from (18.6596, 251.0692) to (15.1449, 242.5839)
  arc A31 centre (14.6596, 263) radius 4 clockwise from (14.6596, 267) to (18.6596, 263)
  arc A32 centre (0.4576, 255) radius 12 clockwise from (-0.5298, 266.9593) to (0.4576, 267)
  arc A33 centre (-121.7, 244.955) radius 12 clockwise from (-123.6681, 256.7925) to (-121.7, 256.955)
  arc A34 centre (-125.9689, 244.5617) radius 12 clockwise from (-136.7133, 249.9055) to (-126.9563, 256.521)
  arc A35 centre (-251.1911, 46.6796) radius 12 clockwise from (-240.4466, 41.3358) to (-247.2657, 35.3398)
  arc A36 centre (-243.3404, 24) radius 12 clockwise from (-255.3404, 24) to (-247.2657, 35.3398)
  circle C6 centre (-115.7, 197.705) radius 1.5
  arc A37 centre (-184.918, 99.0895) radius 12 clockwise from (-176.4327, 90.6042) to (-195.6625, 104.4333)
  arc A38 centre (-145.7, 177.9426) radius 12 clockwise from (-156.4445, 183.2864) to (-133.7, 177.9426)
  arc A39 centre (-145.7, 138.3075) radius 12 clockwise from (-133.7, 138.3075) to (-137.2147, 129.8223)
  arc A40 centre (-85.7, 235.8456) radius 12 clockwise from (-97.7, 235.8456) to (-86.6874, 247.805)
  arc A41 centre (-44.7837, 239.2239) radius 12 clockwise from (-45.7711, 251.1832) to (-36.2984, 230.7386)
  arc A42 centre (-85.7, 198.3075) radius 12 clockwise from (-77.2147, 189.8223) to (-97.7, 198.3075)
  arc A43 centre (-119.5787, 215.5763) radius 3 clockwise from (-117.4574, 213.455) to (-121.7, 217.6976)
  arc A44 centre (-119.5787, 242.8337) radius 3 clockwise from (-121.7, 240.7124) to (-117.4574, 244.955)
  arc A45 centre (-111.8213, 242.8337) radius 3 clockwise from (-113.9426, 244.955) to (-109.7, 240.7124)
  arc A46 centre (-111.8213, 215.5763) radius 3 clockwise from (-109.7, 217.6976) to (-113.9426, 213.455)
  arc A47 centre (-119.5787, 179.8337) radius 3 clockwise from (-121.7, 177.7124) to (-117.4574, 181.955)
  arc A48 centre (-111.8213, 179.8337) radius 3 clockwise from (-113.9426, 181.955) to (-109.7, 177.7124)
  arc A49 centre (-111.8213, 152.5763) radius 3 clockwise from (-109.7, 154.6976) to (-113.9426, 150.455)
  arc A50 centre (-119.5787, 152.5763) radius 3 clockwise from (-117.4574, 150.455) to (-121.7, 154.6976)
  arc A51 centre (-242.3091, 9.8787) radius 3 clockwise from (-244.4304, 12) to (-239.478, 10.8712)
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extrude "Extrusion95" add sketch "Skizze94" profile of A34 L40 A35 A36 L61 against normal blind 12
chamfer "Fase10" distance 3 Rotate Angle 45
chamfer "Fase11" distance 3 Rotate Angle 45
sketch "Skizze95" plane through (362.0031, 0, 0) normal (-1, 0, 0) x axis (0, -1, 0)
  line L1 (-176.4327, 90.6042) -> (-137.2147, 129.8223)
  line L2 (-156.4445, 183.2864) -> (-195.6625, 104.4333)
  line L3 (-133.7, 138.3075) -> (-133.7, 177.9426)
  line L4 (-97.7, 235.8456) -> (-97.7, 198.3075)
  line L5 (-45.7711, 251.1832) -> (-86.6874, 247.805)
  line L6 (-77.2147, 189.8223) -> (-36.2984, 230.7386)
  line L7 (-117.4574, 213.455) -> (-113.9426, 213.455)
  line L8 (-121.7, 240.7124) -> (-121.7, 217.6976)
  line L9 (-113.9426, 244.955) -> (-117.4574, 244.955)
  line L10 (-109.7, 217.6976) -> (-109.7, 240.7124)
  line L11 (-121.7, 177.7124) -> (-121.7, 154.6976)
  line L12 (-113.9426, 181.955) -> (-117.4574, 181.955)
  line L13 (-109.7, 154.6976) -> (-109.7, 177.7124)
  line L14 (-117.4574, 150.455) -> (-113.9426, 150.455)
  line L15 (16.2993, 266.6485) -> (-239.478, 10.8712)
  line L16 (0.4576, 267) -> (14.6596, 267)
  line L17 (-121.7, 256.955) -> (-0.5298, 266.9593)
  line L18 (-126.9563, 256.521) -> (-123.6681, 256.7925)
  line L19 (-253.9338, 29.6373) -> (-136.5623, 250.199)
  line L20 (-255.3404, 12) -> (-255.3404, 24)
  line L21 (-244.4304, 12) -> (-255.3404, 12)
  line L22 (3.2487, 270) -> (14.6596, 270)
  line L23 (3.2487, 267) -> (3.2487, 270)
  line L24 (14.6596, 267) -> (3.2487, 267)
  line L25 (18.6596, 263.0692) -> (18.659, 263.0698)
  line L26 (18.659, 263.0686) -> (18.6596, 263.0692)
  line L27 (18.6596, 251.0692) -> (18.6596, 263)
  line L28 (13.069, 240.508) -> (15.1449, 242.5839)
  line L29 (15.1903, 238.3866) -> (13.069, 240.508)
  line L30 (17.2662, 240.4626) -> (15.1903, 238.3866)
  line L31 (21.6596, 263) -> (21.6596, 251.0692)
  circle C1 centre (-115.7, 197.705) radius 1.5
  arc A1 centre (-184.918, 99.0895) radius 12 clockwise from (-176.4327, 90.6042) to (-195.6625, 104.4333)
  arc A2 centre (-145.7, 177.9426) radius 12 clockwise from (-156.4445, 183.2864) to (-133.7, 177.9426)
  arc A3 centre (-145.7, 138.3075) radius 12 clockwise from (-133.7, 138.3075) to (-137.2147, 129.8223)
  arc A4 centre (-85.7, 235.8456) radius 12 clockwise from (-97.7, 235.8456) to (-86.6874, 247.805)
  arc A5 centre (-44.7837, 239.2239) radius 12 clockwise from (-45.7711, 251.1832) to (-36.2984, 230.7386)
  arc A6 centre (-85.7, 198.3075) radius 12 clockwise from (-77.2147, 189.8223) to (-97.7, 198.3075)
  arc A7 centre (-119.5787, 215.5763) radius 3 clockwise from (-117.4574, 213.455) to (-121.7, 217.6976)
  arc A8 centre (-119.5787, 242.8337) radius 3 clockwise from (-121.7, 240.7124) to (-117.4574, 244.955)
  arc A9 centre (-111.8213, 242.8337) radius 3 clockwise from (-113.9426, 244.955) to (-109.7, 240.7124)
  arc A10 centre (-111.8213, 215.5763) radius 3 clockwise from (-109.7, 217.6976) to (-113.9426, 213.455)
  arc A11 centre (-119.5787, 179.8337) radius 3 clockwise from (-121.7, 177.7124) to (-117.4574, 181.955)
  arc A12 centre (-111.8213, 179.8337) radius 3 clockwise from (-113.9426, 181.955) to (-109.7, 177.7124)
  arc A13 centre (-111.8213, 152.5763) radius 3 clockwise from (-109.7, 154.6976) to (-113.9426, 150.455)
  arc A14 centre (-119.5787, 152.5763) radius 3 clockwise from (-117.4574, 150.455) to (-121.7, 154.6976)
  arc A15 centre (-242.3091, 9.8787) radius 3 clockwise from (-244.4304, 12) to (-239.478, 10.8712)
  arc A16 centre (14.6596, 263) radius 4 clockwise from (14.6596, 267) to (16.2993, 266.6485)
  arc A17 centre (0.4576, 255) radius 12 clockwise from (-0.5298, 266.9593) to (0.4576, 267)
  arc A18 centre (-121.7, 244.955) radius 12 clockwise from (-123.6681, 256.7925) to (-121.7, 256.955)
  arc A19 centre (-125.9689, 244.5617) radius 12 clockwise from (-136.5623, 250.199) to (-126.9563, 256.521)
  arc A20 centre (-243.3404, 24) radius 12 clockwise from (-255.3404, 24) to (-253.9338, 29.6373)
  arc A21 centre (14.6596, 263) radius 7 clockwise from (14.6596, 270) to (21.6596, 263)
  arc A22 centre (14.6596, 263) radius 4 clockwise from (14.6596, 267) to (18.659, 263.0698)
  arc A23 centre (14.6596, 263) radius 4 clockwise from (18.659, 263.0686) to (18.6596, 263)
  arc A24 centre (6.6596, 251.0692) radius 12 clockwise from (18.6596, 251.0692) to (15.1449, 242.5839)
  arc A25 centre (6.6596, 251.0692) radius 15 clockwise from (21.6596, 251.0692) to (17.2662, 240.4626)
  arc A26 centre (6.7487, 267) radius 3.5 clockwise from (10.2487, 267) to (3.2487, 267)
  arc A27 centre (15.5438, 242.9828) radius 3.5 clockwise from (13.069, 240.508) to (17.4864, 245.8942)
  point P82 (6.7487, 267)
  point P83 (10.2487, 267)
  point P84 (17.4864, 245.8942)
  point P77 (13.069, 240.508)
  point P81 (15.5438, 242.9828)
  point P68 (3.2487, 267)
  coincident L24 P82
  coincident L16 P83
  coincident A24 P84
  dimension "d539" diameter A27 = 7
  dimension "d540" distance P77 P81 = 3.5
  dimension "d541" diameter A26 = 7
  dimension "d542" distance P68 P82 = 3.5
extrude "Extrusion96" add sketch "Skizze95" profile of L16 L24 A24 L28 A27 A26 against normal blind 13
